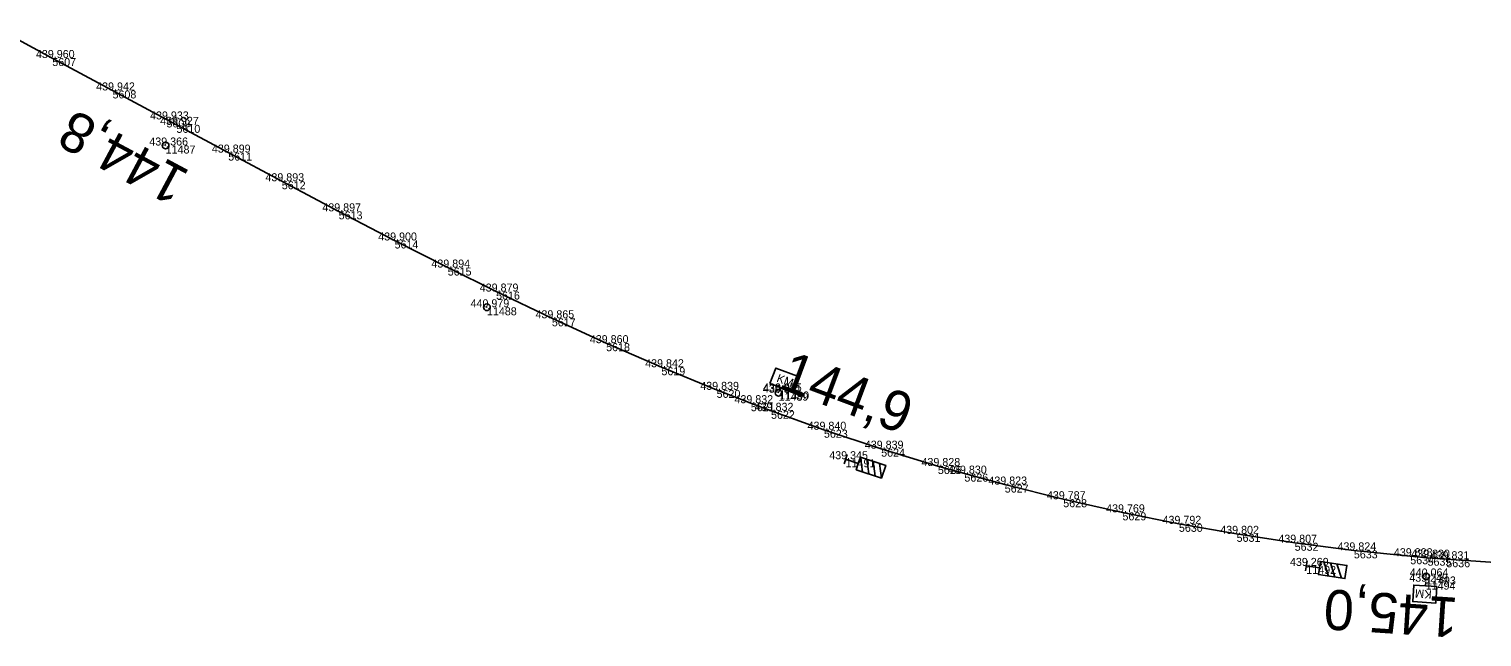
# Model space of a CAD drawing. Extents: x -654154 to -652650, y -1166925 to -1164904.
# Drawn here: x -653276.3 to -653058.4, y -1166925.2 to -1166834 of the extents above; entities that cross this region are included whole.
import ezdxf

# ---------------------------------------------------------------- set-up
doc = ezdxf.new("R2010")
doc.units = 0
for name, color, linetype in [('Vrstva 1', 7, 'Continuous'), ('Vrstva 50', 7, 'Continuous'), ('Vrstva 60', 7, 'Continuous'), ('Vrstva 61', 7, 'Continuous'), ('Vrstva 7', 7, 'Continuous')]:
    doc.layers.add(name, color=color, linetype=linetype)

msp = doc.modelspace()

# ---------------------------------------------------------------- linework, layer by layer
at = {"layer": 'Vrstva 1'}
msp.add_lwpolyline([(-653280.84, -1166834.02), (-653272.79, -1166838.36), (-653263.76, -1166843.22), (-653255.67, -1166847.57), (-653254.17, -1166848.38), (-653246.41, -1166852.54), (-653238.38, -1166856.84), (-653229.85, -1166861.35), (-653221.47, -1166865.72), (-653213.5, -1166869.78), (-653206.25, -1166873.38), (-653197.89, -1166877.39), (-653189.75, -1166881.12), (-653181.46, -1166884.73), (-653173.19, -1166888.12), (-653168.06, -1166890.12), (-653165.03, -1166891.26), (-653157.1, -1166894.1), (-653148.52, -1166896.94), (-653140.02, -1166899.54), (-653136.04, -1166900.68), (-653129.99, -1166902.32), (-653121.22, -1166904.52), (-653112.34, -1166906.49), (-653103.88, -1166908.21), (-653095.23, -1166909.71), (-653086.52, -1166911.04), (-653077.65, -1166912.19), (-653069.19, -1166913.07), (-653066.6, -1166913.29), (-653063.79, -1166913.52), (-653054.19, -1166914.15)], dxfattribs=at)
at = {"layer": 'Vrstva 50'}
msp.add_line((-653207.67, -1166875.74), (-653207.57, -1166875.74), dxfattribs=at)
msp.add_circle((-653207.62, -1166875.74), 0.5, dxfattribs=at)
at = {"layer": 'Vrstva 60'}
for p, q in [((-653272.79, -1166838.36), (-653272.79, -1166838.36)), ((-653263.76, -1166843.22), (-653263.76, -1166843.22)), ((-653255.67, -1166847.57), (-653255.67, -1166847.57)), ((-653254.17, -1166848.38), (-653254.17, -1166848.38)), ((-653255.79, -1166851.48), (-653255.79, -1166851.48)), ((-653246.41, -1166852.54), (-653246.41, -1166852.54)), ((-653238.38, -1166856.84), (-653238.38, -1166856.84)), ((-653229.85, -1166861.35), (-653229.85, -1166861.35)), ((-653221.47, -1166865.72), (-653221.47, -1166865.72)), ((-653213.5, -1166869.78), (-653213.5, -1166869.78)), ((-653206.25, -1166873.38), (-653206.25, -1166873.38)), ((-653207.62, -1166875.74), (-653207.62, -1166875.74)), ((-653197.89, -1166877.39), (-653197.89, -1166877.39)), ((-653189.75, -1166881.12), (-653189.75, -1166881.12)), ((-653181.46, -1166884.73), (-653181.46, -1166884.73)), ((-653173.19, -1166888.12), (-653173.19, -1166888.12)), ((-653163.78, -1166888.36), (-653163.78, -1166888.36)), ((-653168.06, -1166890.12), (-653168.06, -1166890.12)), ((-653163.89, -1166888.55), (-653163.89, -1166888.55)), ((-653165.03, -1166891.26), (-653165.03, -1166891.26)), ((-653157.1, -1166894.1), (-653157.1, -1166894.1)), ((-653148.52, -1166896.94), (-653148.52, -1166896.94)), ((-653153.85, -1166898.52), (-653153.85, -1166898.52)), ((-653140.02, -1166899.54), (-653140.02, -1166899.54)), ((-653136.04, -1166900.68), (-653136.04, -1166900.68)), ((-653129.99, -1166902.32), (-653129.99, -1166902.32)), ((-653121.22, -1166904.52), (-653121.22, -1166904.52)), ((-653112.34, -1166906.49), (-653112.34, -1166906.49)), ((-653103.88, -1166908.21), (-653103.88, -1166908.21)), ((-653095.23, -1166909.71), (-653095.23, -1166909.71)), ((-653086.52, -1166911.04), (-653086.52, -1166911.04)), ((-653077.65, -1166912.19), (-653077.65, -1166912.19)), ((-653084.78, -1166914.52), (-653084.78, -1166914.52)), ((-653069.19, -1166913.07), (-653069.19, -1166913.07)), ((-653066.6, -1166913.29), (-653066.6, -1166913.29)), ((-653063.79, -1166913.52), (-653063.79, -1166913.52)), ((-653066.82, -1166916.1), (-653066.82, -1166916.1)), ((-653066.88, -1166916.89), (-653066.88, -1166916.89))]:
    msp.add_line(p, q, dxfattribs=at)
at = {"layer": 'Vrstva 7'}
for p, q in [((-653255.74, -1166851.51), (-653255.83, -1166851.46)), ((-653163.78, -1166888.36), (-653163.56, -1166887.78)), ((-653163.93, -1166888.53), (-653163.84, -1166888.57)), ((-653153.61, -1166897.81), (-653154.08, -1166899.23)), ((-653151.64, -1166898.2), (-653151.31, -1166900.41)), ((-653150.37, -1166900.72), (-653150.69, -1166898.51)), ((-653149.74, -1166898.83), (-653149.42, -1166901.04)), ((-653148.47, -1166901.35), (-653148.79, -1166899.14)), ((-653084.67, -1166913.78), (-653084.89, -1166915.26)), ((-653082.16, -1166913.91), (-653081.47, -1166916.04)), ((-653080.48, -1166916.19), (-653081.17, -1166914.06)), ((-653080.18, -1166914.21), (-653079.49, -1166916.34)), ((-653066.77, -1166916.11), (-653066.87, -1166916.1)), ((-653066.88, -1166916.89), (-653066.92, -1166917.51))]:
    msp.add_line(p, q, dxfattribs=at)
for points in [[(-653165.19, -1166887.17), (-653164.32, -1166884.85), (-653161.05, -1166886.07), (-653161.92, -1166888.39)], [(-653065.19, -1166917.62), (-653065.35, -1166920.1), (-653068.83, -1166919.87), (-653068.67, -1166917.39)]]:
    msp.add_lwpolyline(points, close=True, dxfattribs=at)
for points in [[(-653153.85, -1166898.52), (-653151.95, -1166899.15), (-653152.26, -1166900.1), (-653148.47, -1166901.35), (-653147.84, -1166899.45), (-653151.64, -1166898.2), (-653151.95, -1166899.15)], [(-653084.78, -1166914.52), (-653082.8, -1166914.83), (-653082.95, -1166915.81), (-653079, -1166916.42), (-653078.7, -1166914.44), (-653082.65, -1166913.84), (-653082.8, -1166914.83)]]:
    msp.add_lwpolyline(points, dxfattribs=at)
for centre in [(-653255.79, -1166851.48), (-653163.89, -1166888.55), (-653066.82, -1166916.1)]:
    msp.add_circle(centre, 0.5, dxfattribs=at)

# ---------------------------------------------------------------- texts
at = {"layer": 'Vrstva 60'}
for s, p in [('5607', (-653272.79, -1166839.56)), ('5608', (-653263.76, -1166844.42)), ('5609', (-653255.67, -1166848.77)), ('5610', (-653254.17, -1166849.58)), ('11487', (-653255.79, -1166852.68)), ('5611', (-653246.41, -1166853.74)), ('5612', (-653238.38, -1166858.04)), ('5613', (-653229.85, -1166862.55)), ('5614', (-653221.47, -1166866.92)), ('5615', (-653213.5, -1166870.98)), ('5616', (-653206.25, -1166874.58)), ('11488', (-653207.62, -1166876.94)), ('5617', (-653197.89, -1166878.59)), ('5618', (-653189.75, -1166882.32)), ('5619', (-653181.46, -1166885.93)), ('5620', (-653173.19, -1166889.32)), ('11490', (-653163.78, -1166889.56)), ('5621', (-653168.06, -1166891.32)), ('11489', (-653163.89, -1166889.75)), ('5622', (-653165.03, -1166892.46)), ('5623', (-653157.1, -1166895.3)), ('5624', (-653148.52, -1166898.14)), ('11491', (-653153.85, -1166899.72)), ('5625', (-653140.02, -1166900.74)), ('5626', (-653136.04, -1166901.88)), ('5627', (-653129.99, -1166903.52)), ('5628', (-653121.22, -1166905.72)), ('5629', (-653112.34, -1166907.69)), ('5630', (-653103.88, -1166909.41)), ('5631', (-653095.23, -1166910.91)), ('5632', (-653086.52, -1166912.25)), ('5633', (-653077.65, -1166913.39)), ('11492', (-653084.78, -1166915.72)), ('5634', (-653069.19, -1166914.27)), ('5635', (-653066.6, -1166914.49)), ('5636', (-653063.79, -1166914.72)), ('11493', (-653066.82, -1166917.3)), ('11494', (-653066.88, -1166918.08))]:
    msp.add_text(s, height=1.2, dxfattribs=at).set_placement(p)
at = {"layer": 'Vrstva 61'}
for s, p in [('439.960', (-653275.24, -1166838.36)), ('439.942', (-653266.21, -1166843.22)), ('439.933', (-653258.13, -1166847.57)), ('439.927', (-653256.62, -1166848.38)), ('439.366', (-653258.24, -1166851.48)), ('439.899', (-653248.86, -1166852.54)), ('439.893', (-653240.83, -1166856.84)), ('439.897', (-653232.3, -1166861.35)), ('439.900', (-653223.92, -1166865.72)), ('439.894', (-653215.95, -1166869.78)), ('439.879', (-653208.7, -1166873.38)), ('440.979', (-653210.08, -1166875.74)), ('439.865', (-653200.34, -1166877.39)), ('439.860', (-653192.2, -1166881.12)), ('439.842', (-653183.9, -1166884.73)), ('439.839', (-653175.64, -1166888.12)), ('439.371', (-653166.25, -1166888.55)), ('438.955', (-653166.23, -1166888.36)), ('439.832', (-653170.51, -1166890.12)), ('439.832', (-653167.47, -1166891.26)), ('439.840', (-653159.55, -1166894.1)), ('439.839', (-653150.97, -1166896.94)), ('439.345', (-653156.3, -1166898.52)), ('439.828', (-653142.47, -1166899.54)), ('439.830', (-653138.49, -1166900.68)), ('439.823', (-653132.44, -1166902.32)), ('439.787', (-653123.67, -1166904.52)), ('439.769', (-653114.79, -1166906.49)), ('439.792', (-653106.33, -1166908.21)), ('439.802', (-653097.68, -1166909.71)), ('439.807', (-653088.97, -1166911.04)), ('439.824', (-653080.1, -1166912.19)), ('439.828', (-653071.65, -1166913.07)), ('439.830', (-653069.05, -1166913.29)), ('439.831', (-653066.14, -1166913.52)), ('439.269', (-653087.23, -1166914.52)), ('439.249', (-653069.34, -1166916.89)), ('440.064', (-653069.27, -1166916.1))]:
    msp.add_text(s, height=1.2, dxfattribs=at).set_placement(p)
at = {"layer": 'Vrstva 7'}
for s, height, rotation, p in [('144,8', 6, 151.8085, (-653251.92, -1166855.42)), ('144,9', 6, 339.4977, (-653164.11, -1166887.79)), ('KM', 1.247, 339.4977, (-653164.29, -1166886.85)), ('145,0', 6, 176.2434, (-653061.88, -1166919.32)), ('KM', 1.247, 176.2434, (-653065.95, -1166918.19))]:
    msp.add_text(s, height=height, rotation=rotation, dxfattribs=at).set_placement(p)

doc.saveas('drawing.dxf')
